// Mitsubishi GX Works2 project: 模拟量0-10V读取   PLC: FX3U/FX3UC

PROGRAM MAIN
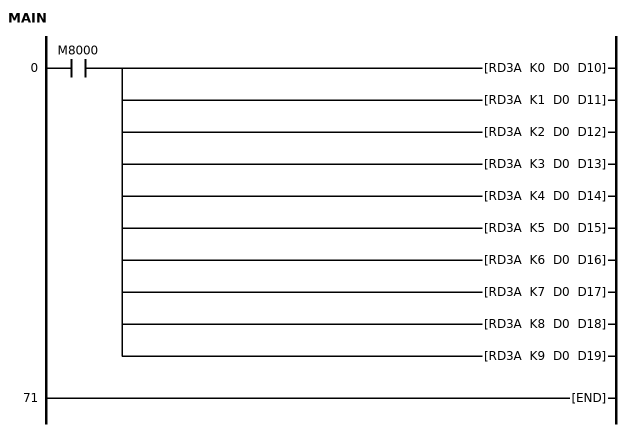
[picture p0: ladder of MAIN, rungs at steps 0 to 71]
0     LD      M8000
      RD3A    K0 D0 D10
      RD3A    K1 D0 D11
      RD3A    K2 D0 D12
      RD3A    K3 D0 D13
      RD3A    K4 D0 D14
      RD3A    K5 D0 D15
      RD3A    K6 D0 D16
      RD3A    K7 D0 D17
      RD3A    K8 D0 D18
      RD3A    K9 D0 D19
71    END
END_PROGRAM
